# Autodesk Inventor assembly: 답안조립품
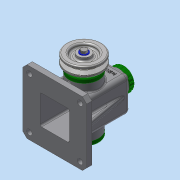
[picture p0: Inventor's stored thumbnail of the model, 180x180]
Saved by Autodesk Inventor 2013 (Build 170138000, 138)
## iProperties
Created: 2018-10
Part Number: 답안조립품
Document SubType Name: Assembly
Designer: Administrator
Author: Administrator
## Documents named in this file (14)
- C:\Users\Administrator\Desktop\481013V1018\답안조립품.iam
- C:\Users\Administrator\Desktop\481013V1018\본체.ipt
- C:\Users\Administrator\Desktop\481013V1018\V-벨트풀리.ipt
- C:\Users\Administrator\Desktop\481013V1018\뒤커버.ipt
- C:\Users\Administrator\Desktop\481013V1018\멈춤링 15 x 1.ipt
- C:\Users\Administrator\Desktop\481013V1018\베어링 15 x 35 x 11.ipt
- C:\Users\Administrator\Desktop\481013V1018\볼트 M4 x 10.ipt
- C:\Users\Administrator\Desktop\481013V1018\볼트 M6 x 12.ipt
- C:\Users\Administrator\Desktop\481013V1018\상부캡.ipt
- C:\Users\Administrator\Desktop\481013V1018\앞커버.ipt
- C:\Users\Administrator\Desktop\481013V1018\오일실 15 25 7.ipt
- C:\Users\Administrator\Desktop\481013V1018\와셔.ipt
- C:\Users\Administrator\Desktop\481013V1018\축.ipt
- C:\Users\Administrator\Desktop\481013V1018\키 5 x 5 x 14.ipt
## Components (1 placed, 1 different names)
1. V-벨트풀리:1 — 플러쉬:1
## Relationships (1: Flush 1)
- 플러쉬:1 [Flush]: V-벨트풀리:1
